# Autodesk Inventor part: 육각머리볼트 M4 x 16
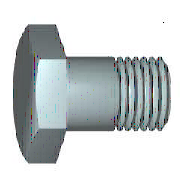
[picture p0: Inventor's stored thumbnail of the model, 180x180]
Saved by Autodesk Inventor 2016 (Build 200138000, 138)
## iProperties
IsCustomPart: 0
Created: 2012-02
Part Number: 육각머리볼트 M4 x 16
Material: 강철, 연강
Description: 6각 머리 볼트 및 6각 머리 나사
Document SubType Name: Modeling
Standard: KS B 1002
Designer: mduedu
Standards Organization: KS
Language: ko-KR
Size Designation: A + B M4 x 16
Categories: <MemberInstance><Categories><Category DisplayName="조임쇠" InternalName="e4da775c-781d-43d5-af7c-5136215cf5a6" Mnemonic="FSTN"><Category DisplayName="볼트" InternalN
Density: 7.86 g/cm^3
Mass: 2.45486 g
Surface Area: 3.4613 cm^2
Volume: 0.312323 cm^3
Appearance: 강철
Author: mduedu
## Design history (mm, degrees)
sketch "스케치1"
  geometry: L1 (0, 2.94)-(0, 2); L2 (2.1, 2)-(16, 2); L3 (16, 2)-(16, 0); L4 (16, 0)-(-0.4, 0); L5 (-3.68, 0)-(19.28, 0) reference; L6 (-0.4, 0)-(-0.4, 2.94); L7 (-0.4, 2.94)-(0, 2.94); L8 (2.1, 2)-(1.67, 2); L9 (1.67, 2)-(0, 2); L10 (0, -0.588)-(0, 3.528) reference
  constraints: 16 end point, 2 collinear, 2 perpendicular, 1 parallel
  dimensions: "d0" = 16 distance between parallel lines of L3 L1 (= NLG); "d1" = 13.9 distance from line of L2.start L3 (= GEL); "d2" = 4 diameter of L2 L4 (= GD); "d9" = 0.4001 distance between parallel lines of L6 L1 (computed from SD); "d10" = 5.88 diameter of L7 L4 (= SD2); "d13" = 0.42952 distance of L2.start L8.end (computed from GAL); "d14" = 4 diameter of L9 L4 (= BDM)
revolve "본체" sketch "스케치1" stored, may be unused: angle "d12" = 90 deg
sketch "스케치2"
  geometry: L1 (0, 4.041)-(3.5, 2.021); L2 (3.5, 2.021)-(3.5, -2.021); L3 (3.5, -2.021)-(0, -4.041); L4 (0, -4.041)-(-3.5, -2.021); L5 (-3.5, -2.021)-(-3.5, 2.021); L6 (-3.5, 2.021)-(0, 4.041); 2 further points
  constraints: 12 end point, 1 coincident, 1 vertical, 11 other
  dimensions: "d11" = 7 distance between parallel lines of L5 L2 (= SW)
extrude "머리" join sketch "스케치2" distance "d3" = 2.4 (= KOH - SD); taper "d4" = 0 deg
sketch "스케치4"
  geometry: L1 (-2.8, 3.5)-(-2.8, 4.041); L2 (-2.8, 4.041)-(-2.487, 4.041); L3 (-2.487, 4.041)-(-2.8, 3.5); L4 (-3.28, 0)-(0.08, 0) reference; L5 (-0.4, 4.041)-(-2.8, 4.041) reference; L6 (-2.8, 2.021)-(-2.8, 4.041) reference
  constraints: 6 end point, 2 collinear, 1 perpendicular, 1 vertical
  dimensions: "d5" = 30 deg angle of L3 L1 (= ANG1); "d19" = 7 diameter of L1.start L4 (= SW0)
revolve "모따기1" sketch "스케치4" stored, may be unused: angle "d21" = 90 deg
workplane "Work Plane1"
body "Solid1"
feature "스레드" dims "d15" = 13.9 (= GEL), "d16" = 0
chamfer "모따기2" distance "d6" = 0.42941 (= -0.5 x SPD + 0.5 x GD); stored, may be unused: second distance "d7" = 0.42952 (computed from GUL), angle "d55" = 45 deg
other parameters: "NLG" = 16 [user parameter; used in 1 equation term], "GD" = 4 (= NND) [user parameter; used in 2 equation terms], "BDM" = 4 (= NND) [user parameter; used in 1 equation term], "KOH" = 2.8 [user parameter; used in 1 equation term], "GEL" = 13.9 [user parameter; used in 2 equation terms], "SW" = 7 [user parameter; used in 3 equation terms], "SW0" = 7 (= SW) [user parameter; used in 1 equation term], "SPD" = 3.14117 (= NND - 1.2269 x PTC) [user parameter; used in 1 equation term], "SD2" = 5.88 (= SDH) [user parameter; used in 1 equation term], "SD" = 0.4 [user parameter; used in 2 equation terms], "ANG1" = 30 deg [user parameter; used in 1 equation term], "GAL" = 0.42941 (= 0.61345 x PTC) [user parameter; used in 1 equation term], "GUL" = 0.42941 (= 0.61345 x PTC) [user parameter; used in 1 equation term], "d8" = 0, "RR" = 0.2 [user parameter], "d57" = 0, "d58" = 0, "TPU" = 14.28571 (computed from PTC) [user parameter], "GD1" = 3.14117 (= THREADDIA - 1.2269 x PTC) [user parameter], "THREADDIA" = 4 [user parameter; used in 1 equation term], "SDH" = 5.88 [user parameter; used in 1 equation term], "SDHG" = 2.1 [user parameter], "TOA" = 30 deg [user parameter], "PTC" = 0.7 [user parameter; used in 5 equation terms], "NND" = 4 [user parameter; used in 3 equation terms], "E0" = 8.085 (= 1.155 x SW) [user parameter]
